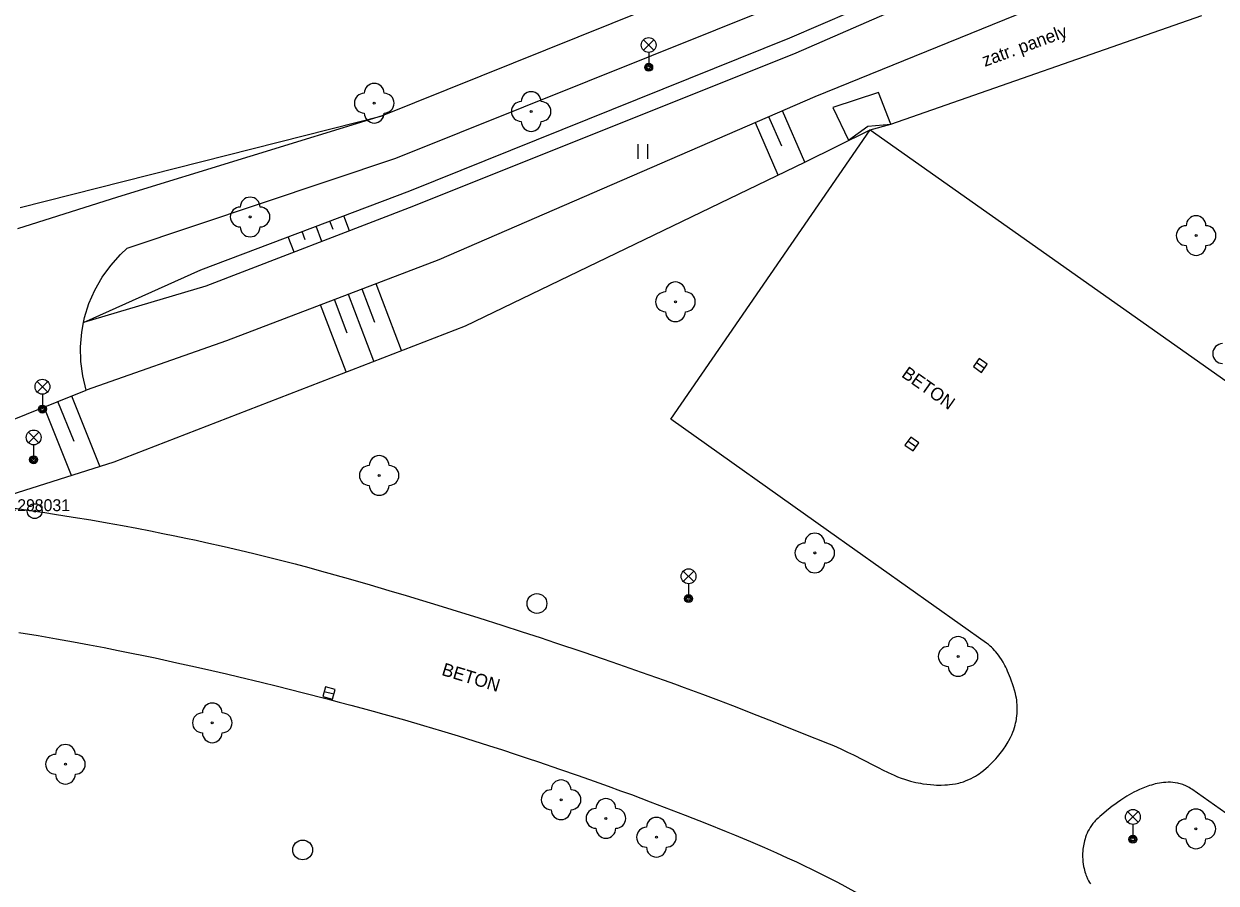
# Model space of a CAD drawing. Extents: x -539515 to -538098, y -1182060 to -1180157.
# Drawn here: x -538776.9 to -538716.8, y -1181100.4 to -1181057.1 of the extents above; entities that cross this region are included whole.
import ezdxf

# ---------------------------------------------------------------- set-up
doc = ezdxf.new("R2010")
doc.units = 0
for name, color, linetype in [('Vrstva 10', 7, 'Continuous'), ('Vrstva 11', 7, 'Continuous'), ('Vrstva 14', 7, 'Continuous'), ('Vrstva 15', 7, 'Continuous'), ('Vrstva 21', 7, 'Continuous'), ('Vrstva 22', 7, 'Continuous'), ('Vrstva 23', 7, 'Continuous'), ('Vrstva 27', 7, 'Continuous'), ('Vrstva 33', 7, 'Continuous'), ('Vrstva 36', 7, 'Continuous'), ('Vrstva 40', 7, 'Continuous')]:
    doc.layers.add(name, color=color, linetype=linetype)

msp = doc.modelspace()

# ---------------------------------------------------------------- linework, layer by layer
at = {"layer": 'Vrstva 10'}
for p, q in [((-538744.28, -1181077), (-538734.22, -1181062.4)), ((-538734.22, -1181062.4), (-538683.56, -1181098.18)), ((-538736.31, -1181082.65), (-538744.28, -1181077)), ((-538728.34, -1181088.3), (-538736.31, -1181082.65)), ((-538767.425, -1181089.685), (-538766.698, -1181089.854)), ((-538757.72, -1181092.174), (-538756.752, -1181092.455)), ((-538747.43, -1181095.515), (-538746.809, -1181095.742)), ((-538705.89, -1181104.22), (-538717.99, -1181095.67))]:
    msp.add_line(p, q, dxfattribs=at)
for points in [[(-538785.812, -1181080.674), (-538785.155, -1181080.723), (-538784.63, -1181080.762), (-538783.596, -1181080.844), (-538782.691, -1181080.921), (-538781.9, -1181080.993), (-538781.208, -1181081.059), (-538780.603, -1181081.12), (-538780.073, -1181081.176), (-538779.147, -1181081.279), (-538779.09, -1181081.286), (-538778.453, -1181081.362), (-538777.932, -1181081.427), (-538777.151, -1181081.53), (-538776.37, -1181081.64)], [(-538776.37, -1181081.64), (-538775.865, -1181081.714), (-538775.376, -1181081.788)], [(-538775.376, -1181081.788), (-538774.429, -1181081.938), (-538773.544, -1181082.084), (-538772.716, -1181082.228), (-538771.941, -1181082.367), (-538771.215, -1181082.503), (-538770.536, -1181082.634), (-538769.899, -1181082.761), (-538769.304, -1181082.883), (-538768.746, -1181082.999), (-538768.223, -1181083.111), (-538767.734, -1181083.218), (-538766.818, -1181083.425), (-538766.017, -1181083.611)], [(-538766.017, -1181083.611), (-538765.317, -1181083.779), (-538764.706, -1181083.929)], [(-538764.706, -1181083.929), (-538764.171, -1181084.063), (-538763.236, -1181084.304), (-538762.536, -1181084.489), (-538762.012, -1181084.631), (-538761.225, -1181084.848), (-538760.44, -1181085.07), (-538759.438, -1181085.36), (-538758.501, -1181085.635), (-538757.624, -1181085.896), (-538756.803, -1181086.143), (-538756.035, -1181086.377), (-538755.316, -1181086.599)], [(-538755.316, -1181086.599), (-538753.969, -1181087.021), (-538752.794, -1181087.395), (-538751.767, -1181087.727), (-538750.869, -1181088.022), (-538750.085, -1181088.282), (-538748.714, -1181088.743), (-538747.687, -1181089.093), (-538746.917, -1181089.359)], [(-538777.172, -1181087.755), (-538776.192, -1181087.917), (-538775.275, -1181088.075), (-538774.416, -1181088.23), (-538773.612, -1181088.38), (-538772.859, -1181088.525), (-538772.153, -1181088.664), (-538771.493, -1181088.798), (-538770.873, -1181088.926), (-538770.293, -1181089.048), (-538769.206, -1181089.284), (-538768.256, -1181089.495), (-538767.425, -1181089.685)], [(-538728.153, -1181088.448), (-538728.245, -1181088.371), (-538728.34, -1181088.3)], [(-538727.135, -1181093.062), (-538727.072, -1181092.922), (-538727.018, -1181092.791), (-538726.973, -1181092.667), (-538726.935, -1181092.55), (-538726.903, -1181092.441), (-538726.878, -1181092.338), (-538726.856, -1181092.241), (-538726.839, -1181092.151), (-538726.825, -1181092.066), (-538726.815, -1181091.987), (-538726.8, -1181091.839), (-538726.793, -1181091.71), (-538726.791, -1181091.598), (-538726.792, -1181091.5), (-538726.796, -1181091.416), (-538726.809, -1181091.268), (-538726.823, -1181091.159), (-538726.836, -1181091.078), (-538726.861, -1181090.958), (-538726.89, -1181090.84), (-538726.937, -1181090.671), (-538726.986, -1181090.509), (-538727.035, -1181090.355), (-538727.084, -1181090.21), (-538727.134, -1181090.073), (-538727.183, -1181089.945), (-538727.232, -1181089.826), (-538727.28, -1181089.714), (-538727.327, -1181089.61), (-538727.374, -1181089.514), (-538727.419, -1181089.425), (-538727.509, -1181089.26), (-538727.593, -1181089.12), (-538727.671, -1181089.001), (-538727.743, -1181088.9), (-538727.808, -1181088.815), (-538727.867, -1181088.742), (-538727.921, -1181088.68), (-538728.018, -1181088.576), (-538728.094, -1181088.501), (-538728.153, -1181088.448)], [(-538746.917, -1181089.359), (-538745.763, -1181089.762), (-538744.61, -1181090.17)], [(-538766.698, -1181089.854), (-538766.063, -1181090.004), (-538764.951, -1181090.272), (-538764.118, -1181090.477), (-538762.869, -1181090.79), (-538761.62, -1181091.11), (-538761.008, -1181091.27), (-538760.416, -1181091.427), (-538759.844, -1181091.581), (-538759.29, -1181091.732), (-538758.755, -1181091.881), (-538757.72, -1181092.174)], [(-538744.61, -1181090.17), (-538744.084, -1181090.359), (-538743.592, -1181090.538), (-538742.671, -1181090.879), (-538741.868, -1181091.182), (-538741.166, -1181091.45), (-538739.941, -1181091.926), (-538739.025, -1181092.287), (-538737.652, -1181092.832), (-538736.28, -1181093.38), (-538736.07, -1181093.466), (-538735.875, -1181093.551), (-538735.694, -1181093.633)], [(-538756.752, -1181092.455), (-538755.847, -1181092.724), (-538755.001, -1181092.981), (-538754.209, -1181093.226), (-538753.468, -1181093.46), (-538752.774, -1181093.682), (-538752.125, -1181093.894), (-538751.517, -1181094.094), (-538750.948, -1181094.285), (-538749.883, -1181094.648), (-538748.953, -1181094.971), (-538748.14, -1181095.259), (-538747.43, -1181095.515)], [(-538735.694, -1181093.633), (-538735.356, -1181093.793), (-538735.063, -1181093.938), (-538734.042, -1181094.461), (-538733.786, -1181094.59), (-538733.594, -1181094.686), (-538733.303, -1181094.826), (-538733.01, -1181094.96), (-538732.829, -1181095.037), (-538732.656, -1181095.103), (-538732.491, -1181095.161), (-538732.334, -1181095.211), (-538732.185, -1181095.254), (-538732.045, -1181095.29), (-538731.912, -1181095.321), (-538731.787, -1181095.348), (-538731.669, -1181095.37), (-538731.558, -1181095.389), (-538731.35, -1181095.418), (-538731.167, -1181095.437), (-538731.008, -1181095.449), (-538730.868, -1181095.455), (-538730.746, -1181095.457), (-538730.64, -1181095.457), (-538730.455, -1181095.451), (-538730.317, -1181095.442), (-538730.214, -1181095.432), (-538730.061, -1181095.414), (-538729.91, -1181095.39), (-538729.822, -1181095.373), (-538729.737, -1181095.354), (-538729.657, -1181095.333), (-538729.579, -1181095.311), (-538729.505, -1181095.287), (-538729.363, -1181095.236), (-538729.233, -1181095.181), (-538729.113, -1181095.124), (-538729.002, -1181095.066), (-538728.9, -1181095.007), (-538728.806, -1181094.948), (-538728.718, -1181094.89), (-538728.637, -1181094.832), (-538728.562, -1181094.776), (-538728.492, -1181094.722), (-538728.364, -1181094.614), (-538728.253, -1181094.515), (-538728.157, -1181094.424), (-538728.075, -1181094.341), (-538728.003, -1181094.267), (-538727.879, -1181094.131), (-538727.788, -1181094.026), (-538727.653, -1181093.862), (-538727.52, -1181093.69), (-538727.458, -1181093.605), (-538727.4, -1181093.522), (-538727.347, -1181093.441), (-538727.298, -1181093.362), (-538727.253, -1181093.285), (-538727.211, -1181093.209), (-538727.135, -1181093.062)], [(-538746.809, -1181095.742), (-538746.266, -1181095.942), (-538745.318, -1181096.297), (-538744.608, -1181096.568), (-538743.543, -1181096.98), (-538742.48, -1181097.4), (-538741.488, -1181097.799), (-538741.056, -1181097.976), (-538740.249, -1181098.312), (-538739.546, -1181098.613), (-538738.933, -1181098.881), (-538738.4, -1181099.121), (-538737.936, -1181099.335)], [(-538717.99, -1181095.67), (-538718.055, -1181095.626), (-538718.12, -1181095.586), (-538718.185, -1181095.549), (-538718.25, -1181095.516), (-538718.315, -1181095.486), (-538718.379, -1181095.459), (-538718.443, -1181095.434), (-538718.506, -1181095.413), (-538718.57, -1181095.394), (-538718.633, -1181095.377), (-538718.695, -1181095.363), (-538718.819, -1181095.341), (-538718.942, -1181095.327), (-538719.061, -1181095.319), (-538719.179, -1181095.318), (-538719.294, -1181095.322), (-538719.406, -1181095.331), (-538719.515, -1181095.344), (-538719.622, -1181095.361), (-538719.726, -1181095.381), (-538719.827, -1181095.404), (-538719.925, -1181095.429), (-538720.02, -1181095.456), (-538720.113, -1181095.485), (-538720.203, -1181095.515), (-538720.29, -1181095.546), (-538720.458, -1181095.613), (-538720.617, -1181095.681), (-538720.765, -1181095.751), (-538720.903, -1181095.821), (-538721.032, -1181095.891), (-538721.152, -1181095.959), (-538721.265, -1181096.025), (-538721.369, -1181096.089), (-538721.563, -1181096.215), (-538721.73, -1181096.33), (-538721.875, -1181096.433), (-538721.999, -1181096.527), (-538722.107, -1181096.61), (-538722.291, -1181096.758), (-538722.426, -1181096.872), (-538722.622, -1181097.045), (-538722.717, -1181097.132), (-538722.81, -1181097.22), (-538722.855, -1181097.265), (-538722.898, -1181097.31), (-538722.978, -1181097.404), (-538723.05, -1181097.499), (-538723.115, -1181097.596), (-538723.172, -1181097.693), (-538723.224, -1181097.791), (-538723.269, -1181097.888), (-538723.309, -1181097.984), (-538723.344, -1181098.079), (-538723.374, -1181098.173), (-538723.4, -1181098.265), (-538723.423, -1181098.356), (-538723.441, -1181098.444), (-538723.457, -1181098.53), (-538723.47, -1181098.615), (-538723.479, -1181098.697), (-538723.487, -1181098.776), (-538723.495, -1181098.931), (-538723.496, -1181099.076), (-538723.49, -1181099.211), (-538723.479, -1181099.337), (-538723.464, -1181099.455), (-538723.446, -1181099.563), (-538723.425, -1181099.663), (-538723.402, -1181099.756), (-538723.378, -1181099.841), (-538723.353, -1181099.92), (-538723.327, -1181099.992), (-538723.302, -1181100.059), (-538723.248, -1181100.18), (-538723.196, -1181100.283), (-538723.147, -1181100.369), (-538723.101, -1181100.441)], [(-538737.936, -1181099.335), (-538737.531, -1181099.526), (-538737.179, -1181099.696)], [(-538737.179, -1181099.696), (-538736.871, -1181099.846), (-538736.335, -1181100.116), (-538735.936, -1181100.322)], [(-538735.936, -1181100.322), (-538735.638, -1181100.48), (-538735.192, -1181100.722), (-538734.75, -1181100.97), (-538734.399, -1181101.172), (-538734.137, -1181101.326), (-538733.747, -1181101.561), (-538733.36, -1181101.8), (-538731.941, -1181102.691), (-538730.702, -1181103.474), (-538728.536, -1181104.848)]]:
    msp.add_lwpolyline(points, dxfattribs=at)
at = {"layer": 'Vrstva 11'}
for p, q in [((-538739.389, -1181053.868), (-538758.831, -1181061.694)), ((-538758.154, -1181063.833), (-538738.78, -1181056.061)), ((-538758.831, -1181061.694), (-538772.191, -1181065.795)), ((-538771.702, -1181068.376), (-538758.154, -1181063.833)), ((-538772.191, -1181065.795), (-538777.247, -1181067.406)), ((-538779.48, -1181077.833), (-538773.769, -1181075.54))]:
    msp.add_line(p, q, dxfattribs=at)
for points in [[(-538736.106, -1181061.274), (-538735.314, -1181062.919), (-538734.338, -1181062.227), (-538733.175, -1181062.121), (-538733.801, -1181060.523), (-538736.106, -1181061.274)], [(-538773.769, -1181075.54), (-538773.944, -1181074.82), (-538774.04, -1181074.084), (-538774.057, -1181073.343), (-538773.994, -1181072.604), (-538773.91, -1181072.13), (-538773.851, -1181071.877), (-538773.631, -1181071.169), (-538773.336, -1181070.488), (-538772.97, -1181069.844), (-538772.536, -1181069.243), (-538772.04, -1181068.691), (-538771.702, -1181068.376)]]:
    msp.add_lwpolyline(points, dxfattribs=at)
at = {"layer": 'Vrstva 14'}
for p, q in [((-538738.275, -1181057.756), (-538720.538, -1181050.067)), ((-538720.295, -1181050.803), (-538737.968, -1181058.537)), ((-538719.229, -1181053.507), (-538737, -1181060.742)), ((-538733.175, -1181062.121), (-538717.481, -1181056.636)), ((-538757.436, -1181065.483), (-538738.275, -1181057.756)), ((-538737.968, -1181058.537), (-538757.265, -1181066.25)), ((-538737, -1181060.742), (-538755.984, -1181068.964)), ((-538777.11, -1181066.32), (-538758.831, -1181061.694)), ((-538754.626, -1181072.284), (-538737.51, -1181064.038)), ((-538767.995, -1181069.463), (-538757.436, -1181065.483)), ((-538757.265, -1181066.25), (-538767.736, -1181070.294)), ((-538755.984, -1181068.964), (-538766.696, -1181073.047)), ((-538773.91, -1181072.13), (-538767.995, -1181069.463)), ((-538767.736, -1181070.294), (-538773.91, -1181072.13)), ((-538772.362, -1181079.152), (-538754.626, -1181072.284)), ((-538766.696, -1181073.047), (-538773.769, -1181075.54)), ((-538779.09, -1181081.286), (-538772.362, -1181079.152))]:
    msp.add_line(p, q, dxfattribs=at)
msp.add_lwpolyline([(-538737.51, -1181064.038), (-538734.22, -1181062.4), (-538733.175, -1181062.121)], dxfattribs=at)
at = {"layer": 'Vrstva 15'}
for p, q in [((-538737.51, -1181064.038), (-538738.632, -1181061.449)), ((-538738.863, -1181064.69), (-538740.008, -1181062.045)), ((-538738.678, -1181063.229), (-538739.32, -1181061.747)), ((-538760.488, -1181067.495), (-538760.773, -1181066.741)), ((-538761.888, -1181068.035), (-538762.176, -1181067.27)), ((-538761.316, -1181067.426), (-538761.474, -1181067.005)), ((-538763.287, -1181068.576), (-538763.58, -1181067.799)), ((-538762.719, -1181067.955), (-538762.878, -1181067.534)), ((-538759.201, -1181072.124), (-538759.844, -1181070.435)), ((-538757.86, -1181073.536), (-538759.144, -1181070.168)), ((-538760.602, -1181072.658), (-538761.246, -1181070.97)), ((-538759.259, -1181074.078), (-538760.545, -1181070.703)), ((-538760.658, -1181074.619), (-538761.947, -1181071.237)), ((-538773.078, -1181079.379), (-538774.501, -1181075.834)), ((-538774.512, -1181079.834), (-538775.893, -1181076.393)), ((-538774.386, -1181078.134), (-538775.197, -1181076.113))]:
    msp.add_line(p, q, dxfattribs=at)
at = {"layer": 'Vrstva 21'}
for radius in [0.375, 0.05]:
    msp.add_circle((-538776.37, -1181081.64), radius, dxfattribs=at)
at = {"layer": 'Vrstva 22'}
for centre in [(-538759.24, -1181061.06), (-538751.32, -1181061.48), (-538765.5, -1181066.8), (-538717.77, -1181067.74), (-538744.04, -1181071.08), (-538758.99, -1181079.84), (-538737.01, -1181083.75), (-538729.78, -1181088.97), (-538767.41, -1181092.32), (-538774.82, -1181094.41), (-538749.81, -1181096.2), (-538747.55, -1181097.14), (-538745, -1181098.09), (-538717.78, -1181097.67)]:
    msp.add_circle(centre, 0.05, dxfattribs=at)
for centre, start, end in [((-538759.24, -1181060.56), 0, 180), ((-538759.74, -1181061.06), 90, 270), ((-538758.74, -1181061.06), 270, 90), ((-538751.32, -1181060.98), 0, 180), ((-538751.82, -1181061.48), 90, 270), ((-538750.82, -1181061.48), 270, 90), ((-538759.24, -1181061.56), 180, 0), ((-538751.32, -1181061.98), 180, 0), ((-538766, -1181066.8), 90, 270), ((-538765.5, -1181066.3), 0, 180), ((-538765, -1181066.8), 270, 90), ((-538717.77, -1181067.24), 0, 180), ((-538765.5, -1181067.3), 180, 0), ((-538718.27, -1181067.74), 90, 270), ((-538717.27, -1181067.74), 270, 90), ((-538717.77, -1181068.24), 180, 0), ((-538744.04, -1181070.58), 0, 180), ((-538744.54, -1181071.08), 90, 270), ((-538743.54, -1181071.08), 270, 90), ((-538744.04, -1181071.58), 180, 0), ((-538716.43, -1181073.69), 90, 270), ((-538758.99, -1181079.34), 0, 180), ((-538759.49, -1181079.84), 90, 270), ((-538758.49, -1181079.84), 270, 90), ((-538758.99, -1181080.34), 180, 0), ((-538737.01, -1181083.25), 0, 180), ((-538737.51, -1181083.75), 90, 270), ((-538736.51, -1181083.75), 270, 90), ((-538737.01, -1181084.25), 180, 0), ((-538729.78, -1181088.47), 0, 180), ((-538730.28, -1181088.97), 90, 270), ((-538729.28, -1181088.97), 270, 90), ((-538729.78, -1181089.47), 180, 0), ((-538767.41, -1181091.82), 0, 180), ((-538767.91, -1181092.32), 90, 270), ((-538766.91, -1181092.32), 270, 90), ((-538767.41, -1181092.82), 180, 0), ((-538775.32, -1181094.41), 90, 270), ((-538774.82, -1181093.91), 0, 180), ((-538774.32, -1181094.41), 270, 90), ((-538774.82, -1181094.91), 180, 0), ((-538750.31, -1181096.2), 90, 270), ((-538749.81, -1181095.7), 0, 180), ((-538749.31, -1181096.2), 270, 90), ((-538747.55, -1181096.64), 0, 180), ((-538749.81, -1181096.7), 180, 0), ((-538748.05, -1181097.14), 90, 270), ((-538747.05, -1181097.14), 270, 90), ((-538717.78, -1181097.17), 0, 180), ((-538745.5, -1181098.09), 90, 270), ((-538745, -1181097.59), 0, 180), ((-538744.5, -1181098.09), 270, 90), ((-538718.28, -1181097.67), 90, 270), ((-538717.28, -1181097.67), 270, 90), ((-538747.55, -1181097.64), 180, 0), ((-538717.78, -1181098.17), 180, 0), ((-538745, -1181098.59), 180, 0)]:
    msp.add_arc(centre, 0.5, start, end, dxfattribs=at)
at = {"layer": 'Vrstva 27'}
for p, q in [((-538728.456, -1181074.434), (-538728.864, -1181074.146)), ((-538731.906, -1181078.394), (-538732.314, -1181078.106)), ((-538761.28, -1181090.875), (-538761.764, -1181090.749))]:
    msp.add_line(p, q, dxfattribs=at)
for points in [[(-538728.312, -1181074.23), (-538728.72, -1181073.942), (-538729.008, -1181074.35), (-538728.6, -1181074.638)], [(-538731.762, -1181078.19), (-538732.17, -1181077.902), (-538732.458, -1181078.31), (-538732.05, -1181078.598)], [(-538761.217, -1181090.632), (-538761.702, -1181090.507), (-538761.827, -1181090.992), (-538761.342, -1181091.117)]]:
    msp.add_lwpolyline(points, close=True, dxfattribs=at)
for centre in [(-538751.03, -1181086.3), (-538762.85, -1181098.73)]:
    msp.add_circle(centre, 0.5, dxfattribs=at)
at = {"layer": 'Vrstva 33'}
for p, q in [((-538745.655, -1181058.39), (-538745.125, -1181057.86)), ((-538745.655, -1181057.86), (-538745.125, -1181058.39)), ((-538745.39, -1181058.5), (-538745.39, -1181059.25)), ((-538776.245, -1181075.63), (-538775.715, -1181075.1)), ((-538776.245, -1181075.1), (-538775.715, -1181075.63)), ((-538775.98, -1181075.74), (-538775.98, -1181076.49)), ((-538776.69, -1181078.188), (-538776.16, -1181077.658)), ((-538776.69, -1181077.658), (-538776.16, -1181078.188)), ((-538776.425, -1181078.298), (-538776.425, -1181079.048)), ((-538743.645, -1181085.19), (-538743.115, -1181084.66)), ((-538743.645, -1181084.66), (-538743.115, -1181085.19)), ((-538743.38, -1181085.3), (-538743.38, -1181086.05)), ((-538721.225, -1181097.33), (-538720.695, -1181096.8)), ((-538721.225, -1181096.8), (-538720.695, -1181097.33)), ((-538720.96, -1181097.44), (-538720.96, -1181098.19))]:
    msp.add_line(p, q, dxfattribs=at)
for centre, radius in [((-538745.39, -1181058.125), 0.375), ((-538745.39, -1181059.25), 0.2), ((-538745.39, -1181059.25), 0.145), ((-538745.39, -1181059.25), 0.0876), ((-538775.98, -1181075.365), 0.375), ((-538775.98, -1181076.49), 0.2), ((-538775.98, -1181076.49), 0.145), ((-538775.98, -1181076.49), 0.0876), ((-538776.425, -1181077.923), 0.375), ((-538776.425, -1181079.048), 0.2), ((-538776.425, -1181079.048), 0.145), ((-538776.425, -1181079.048), 0.0876), ((-538743.38, -1181084.925), 0.375), ((-538743.38, -1181086.05), 0.2), ((-538743.38, -1181086.05), 0.145), ((-538743.38, -1181086.05), 0.0876), ((-538720.96, -1181097.065), 0.375), ((-538720.96, -1181098.19), 0.2), ((-538720.96, -1181098.19), 0.145), ((-538720.96, -1181098.19), 0.0876)]:
    msp.add_circle(centre, radius, dxfattribs=at)
at = {"layer": 'Vrstva 36'}
for p, q in [((-538745.927, -1181063.871), (-538745.927, -1181063.121)), ((-538745.427, -1181063.871), (-538745.427, -1181063.121))]:
    msp.add_line(p, q, dxfattribs=at)

# ---------------------------------------------------------------- texts
at = {"layer": 'Vrstva 22'}
msp.add_text('178.29 ', height=0.6, dxfattribs=at).set_placement((-538778.814, -1181081.64))
at = {"layer": 'Vrstva 23'}
msp.add_text('8031', height=0.6, dxfattribs=at).set_placement((-538776.37, -1181081.64))
at = {"layer": 'Vrstva 40'}
for s, rotation, p in [('zatr. panely', 20.03978, (-538728.429, -1181059.23)), ('BETON', 324.76731, (-538732.678, -1181074.832)), ('BETON', 343.15041, (-538755.877, -1181089.899))]:
    msp.add_text(s, height=0.65, rotation=rotation, dxfattribs=at).set_placement(p)

doc.saveas('drawing.dxf')
